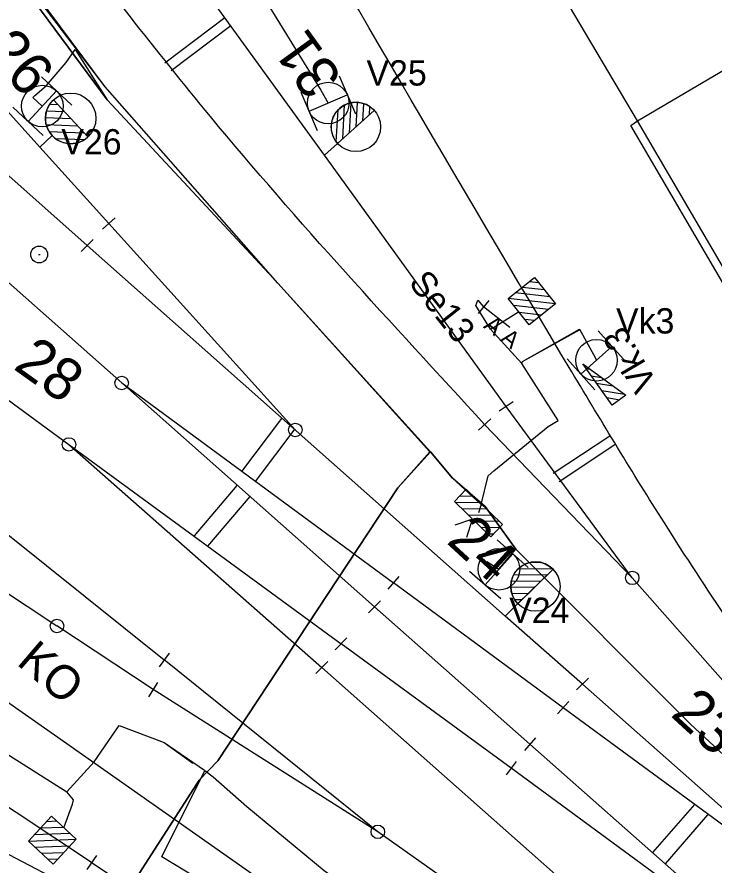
# Model space of a CAD drawing. Extents: x -496570 to -495506, y -1089156 to -1088046.
# Drawn here: x -496040.3 to -495999, y -1088592.2 to -1088542 of the extents above; entities that cross this region are included whole.
import ezdxf

# ---------------------------------------------------------------- set-up
doc = ezdxf.new("R2010")
doc.units = 0
for name, color, linetype in [('11', 7, 'Continuous'), ('14', 7, 'Continuous'), ('15', 7, 'Continuous'), ('20', 7, 'Continuous'), ('27', 7, 'Continuous'), ('39', 7, 'Continuous'), ('54', 7, 'Continuous'), ('PŮVODNÍ_NÁVRH', 7, 'Continuous'), ('SEE', 7, 'Continuous')]:
    doc.layers.add(name, color=color, linetype=linetype)

msp = doc.modelspace()

# ---------------------------------------------------------------- linework, layer by layer
at = {"layer": '11'}
for p, q in [((-496031.528, -1088544.679), (-496027.962, -1088541.996)), ((-496031.147, -1088545.144), (-496027.61, -1088542.482)), ((-496039.013, -1088556.033), (-496038.913, -1088556.033)), ((-496008.511, -1088568.976), (-496005.162, -1088566.778)), ((-496008.167, -1088569.467), (-496004.852, -1088567.292))]:
    msp.add_line(p, q, dxfattribs=at)
for points in [[(-496026.95, -1088568.883), (-496024.582, -1088565.738)], [(-496026.143, -1088569.473), (-496023.8, -1088566.361)], [(-496029.754, -1088572.697), (-496027.23, -1088569.715)], [(-496028.965, -1088573.313), (-496026.466, -1088570.361)], [(-496002.617, -1088591.447), (-496000.13, -1088588.596)], [(-496001.863, -1088592.105), (-495999.348, -1088589.222)]]:
    msp.add_lwpolyline(points, dxfattribs=at)
msp.add_circle((-496038.963, -1088556.033), 0.5, dxfattribs=at)
at = {"layer": '14'}
for p, q in [((-496034.834, -1088554.201), (-496038.935, -1088549.668)), ((-496055.342, -1088566.508), (-496037.913, -1088578.03)), ((-496007.924, -1088582.875), (-496017.979, -1088575.474)), ((-496019.1, -1088576.895), (-496009.888, -1088585.031)), ((-496006.781, -1088581.466), (-496011.354, -1088577.439)), ((-496032.216, -1088581.796), (-496037.913, -1088578.03)), ((-496011.01, -1088586.449), (-496021.082, -1088579.088)), ((-495993.785, -1088605.649), (-496022.225, -1088580.492))]:
    msp.add_line(p, q, dxfattribs=at)
for points in [[(-496036.118, -1088555.5), (-496048.975, -1088544.1), (-496066.196, -1088528.906), (-496086.152, -1088511.349), (-496104.929, -1088494.746), (-496123.588, -1088478.229), (-496142.293, -1088461.701), (-496160.965, -1088445.175), (-496179.891, -1088428.396), (-496198.214, -1088412.189), (-496217.292, -1088395.311), (-496245.811, -1088370.064), (-496264.918, -1088353.145), (-496281.988, -1088338.018), (-496302.247, -1088320.079), (-496322.57, -1088302.076), (-496341.966, -1088284.907), (-496360.552, -1088268.447), (-496378.713, -1088252.378), (-496398.4, -1088234.928), (-496416.447, -1088218.945), (-496437.668, -1088200.162), (-496456.103, -1088183.845), (-496474.042, -1088168.071)], [(-496011.29, -1088565.037), (-496022.068, -1088550.141), (-496029.461, -1088539.924), (-496036.884, -1088529.665), (-496046.952, -1088515.759), (-496054.33, -1088505.532), (-496061.713, -1088495.299), (-496072.458, -1088480.37)], [(-496075.31, -1088545), (-496052.489, -1088563.281), (-496031.561, -1088580.038)], [(-496035.857, -1088592.043), (-496044.874, -1088586.073), (-496053.125, -1088580.797), (-496061.169, -1088575.721), (-496076.529, -1088566.028)], [(-496063.029, -1088566.985), (-496037.138, -1088585.134), (-496023.296, -1088594.829), (-496003.341, -1088609.037)], [(-496037.513, -1088593.285), (-496040.369, -1088591.776), (-496048.068, -1088587.699), (-496063.641, -1088579.453)]]:
    msp.add_lwpolyline(points, dxfattribs=at)
msp.add_circle((-496037.913, -1088578.03), 0.4, dxfattribs=at)
for points in [[(-496012.573, -1088566.09), (-496028.822, -1088547.857), (-496038.151, -1088535.934), (-496051.597, -1088517.251)], [(-495994.179, -1088583.585), (-496001.925, -1088571.928), (-496007.411, -1088562.975), (-496027.558, -1088528.593)], [(-496009.526, -1088642.986), (-496015.368, -1088636.526), (-496021.579, -1088629.917), (-496040.398, -1088611.545), (-496052.231, -1088600.497), (-496064.07, -1088590.377), (-496077.737, -1088579.829), (-496084.463, -1088574.911)]]:
    msp.add_spline(points, degree=3, dxfattribs=at)
at = {"layer": '15'}
for p, q in [((-496021.201, -1088545.449), (-496020.226, -1088547.712)), ((-496038.836, -1088545.509), (-496037.039, -1088547.194)), ((-496039.623, -1088548.149), (-496037.937, -1088546.351)), ((-496023.464, -1088546.424), (-496022.489, -1088548.687)), ((-496022.977, -1088547.555), (-496020.713, -1088546.581)), ((-496040.521, -1088547.306), (-496038.724, -1088548.991)), ((-496009.03, -1088558.131), (-496010.349, -1088557.977)), ((-496009.359, -1088557.715), (-496009.933, -1088557.648)), ((-496008.7, -1088558.547), (-496010.765, -1088558.307)), ((-496008.371, -1088558.962), (-496011.181, -1088558.636)), ((-496008.787, -1088559.291), (-496010.852, -1088559.052)), ((-496009.203, -1088559.621), (-496010.522, -1088559.468)), ((-496009.619, -1088559.95), (-496010.193, -1088559.883)), ((-496005.854, -1088560.56), (-496004.21, -1088562.396)), ((-496006.868, -1088563.122), (-496005.032, -1088561.478)), ((-496007.69, -1088562.204), (-496006.046, -1088564.04)), ((-496006.564, -1088562.783), (-496006.328, -1088562.822)), ((-496006.255, -1088563.214), (-496005.649, -1088563.314)), ((-496005.946, -1088563.645), (-496004.97, -1088563.806)), ((-496005.636, -1088564.077), (-496004.291, -1088564.298)), ((-496005.328, -1088564.507), (-496004.573, -1088564.632)), ((-496005.019, -1088564.938), (-496005.003, -1088564.94)), ((-496011.834, -1088572.933), (-496009.99, -1088574.567)), ((-496012.546, -1088575.594), (-496010.912, -1088573.75)), ((-496013.468, -1088574.777), (-496011.624, -1088576.411)), ((-496038.521, -1088589.598), (-496037.943, -1088589.577)), ((-496038.882, -1088589.986), (-496037.555, -1088589.938)), ((-496039.244, -1088590.375), (-496037.166, -1088590.3)), ((-496039.605, -1088590.763), (-496036.778, -1088590.661)), ((-496039.217, -1088591.124), (-496037.139, -1088591.049)), ((-496038.828, -1088591.486), (-496037.501, -1088591.438)), ((-496038.44, -1088591.847), (-496037.862, -1088591.826))]:
    msp.add_line(p, q, dxfattribs=at)
for points in [[(-496009.939, -1088560.204), (-496011.181, -1088558.636), (-496009.613, -1088557.394), (-496008.371, -1088558.962)], [(-496009.939, -1088560.204), (-496011.181, -1088558.636), (-496009.613, -1088557.394), (-496008.371, -1088558.962)], [(-496038.242, -1088589.299), (-496036.778, -1088590.661), (-496038.141, -1088592.125), (-496039.605, -1088590.763)], [(-496038.242, -1088589.299), (-496036.778, -1088590.661), (-496038.141, -1088592.125), (-496039.605, -1088590.763)]]:
    msp.add_lwpolyline(points, close=True, dxfattribs=at)
for points in [[(-496009.939, -1088560.204), (-496011.181, -1088558.636), (-496009.613, -1088557.394), (-496008.371, -1088558.962), (-496009.939, -1088560.204)], [(-496009.939, -1088560.204), (-496011.181, -1088558.636), (-496009.613, -1088557.394), (-496008.371, -1088558.962), (-496009.939, -1088560.204)], [(-496006.761, -1088562.508), (-496004.2, -1088564.364), (-496005.013, -1088564.947), (-496006.761, -1088562.508)], [(-496006.761, -1088562.508), (-496004.2, -1088564.364), (-496005.013, -1088564.947), (-496006.761, -1088562.508)], [(-496038.242, -1088589.299), (-496036.778, -1088590.661), (-496038.141, -1088592.125), (-496039.605, -1088590.763), (-496038.242, -1088589.299)], [(-496038.242, -1088589.299), (-496036.778, -1088590.661), (-496038.141, -1088592.125), (-496039.605, -1088590.763), (-496038.242, -1088589.299)]]:
    msp.add_lwpolyline(points, dxfattribs=at)
for centre in [(-496021.841, -1088547.065), (-496038.778, -1088547.246), (-496005.947, -1088562.296), (-496011.727, -1088574.667)]:
    msp.add_circle(centre, 1.232, dxfattribs=at)
at = {"layer": '20'}
for p, q in [((-496012.331, -1088558.747), (-496012.949, -1088559.533)), ((-496011.082, -1088560.362), (-496012.64, -1088559.14))]:
    msp.add_line(p, q, dxfattribs=at)
at = {"layer": '27'}
for p, q in [((-496036.081, -1088549.071), (-496038.119, -1088546.869)), ((-496038.119, -1088546.869), (-496036.081, -1088549.071)), ((-496038.345, -1088547.139), (-496037.851, -1088547.159)), ((-496020.981, -1088549.175), (-496020.868, -1088547.18)), ((-496020.586, -1088548.822), (-496020.485, -1088547.049)), ((-496020.19, -1088548.468), (-496020.108, -1088547.027)), ((-496019.794, -1088548.115), (-496019.737, -1088547.102)), ((-496019.398, -1088547.762), (-496019.372, -1088547.285)), ((-496038.596, -1088547.93), (-496037.083, -1088547.989)), ((-496038.531, -1088547.532), (-496037.467, -1088547.574)), ((-496021.367, -1088549.368), (-496021.261, -1088547.473)), ((-496019.114, -1088547.509), (-496021.299, -1088549.458)), ((-496021.298, -1088549.458), (-496019.114, -1088547.509)), ((-496038.552, -1088548.333), (-496036.698, -1088548.404)), ((-496038.384, -1088548.74), (-496036.314, -1088548.819)), ((-496038.201, -1088548.989), (-496038.935, -1088549.668)), ((-496038.019, -1088549.154), (-496036.279, -1088549.221)), ((-496021.299, -1088549.459), (-496022.068, -1088550.141)), ((-496021.299, -1088549.458), (-496021.298, -1088549.458)), ((-496034.458, -1088553.871), (-496035.21, -1088554.531)), ((-496023.791, -1088566.421), (-496034.834, -1088554.201)), ((-496035.76, -1088555.151), (-496036.476, -1088555.849)), ((-496010.876, -1088564.756), (-496011.704, -1088565.318)), ((-496012.203, -1088565.754), (-496012.943, -1088566.426)), ((-496003.83, -1088575.183), (-496012.573, -1088566.09)), ((-496009.838, -1088574.256), (-496009.247, -1088574.263)), ((-496010.845, -1088574.984), (-496008.863, -1088575.008)), ((-496008.524, -1088574.675), (-496010.619, -1088576.719)), ((-496008.516, -1088574.67), (-496010.612, -1088576.713)), ((-496010.554, -1088574.617), (-496008.546, -1088574.642)), ((-496008.517, -1088574.669), (-496008.516, -1088574.67)), ((-496017.656, -1088575.092), (-496018.302, -1088575.856)), ((-496010.986, -1088575.352), (-496009.238, -1088575.374)), ((-496011.024, -1088575.721), (-496009.613, -1088575.738)), ((-496018.752, -1088576.536), (-496019.448, -1088577.254)), ((-496010.968, -1088576.092), (-496009.987, -1088576.104)), ((-496010.803, -1088576.464), (-496010.362, -1088576.47)), ((-496010.62, -1088576.719), (-496011.354, -1088577.439)), ((-496020.735, -1088578.728), (-496021.429, -1088579.448)), ((-496031.268, -1088579.633), (-496031.854, -1088580.443)), ((-496021.873, -1088580.137), (-496022.577, -1088580.847)), ((-496031.953, -1088581.371), (-496032.479, -1088582.221)), ((-496006.428, -1088581.112), (-496007.134, -1088581.82)), ((-496007.584, -1088582.509), (-496008.264, -1088583.241)), ((-496009.563, -1088584.651), (-496010.213, -1088585.411)), ((-496010.716, -1088586.045), (-496011.304, -1088586.853)), ((-496035.576, -1088591.63), (-496036.138, -1088592.456))]:
    msp.add_line(p, q, dxfattribs=at)
for points in [[(-496022.068, -1088550.141), (-496029.461, -1088539.924), (-496036.884, -1088529.665)], [(-496038.935, -1088549.668), (-496047.32, -1088540.34), (-496055.467, -1088530.486)], [(-496019.1, -1088576.895), (-496034.077, -1088563.64), (-496044.26, -1088554.627)], [(-496011.354, -1088577.439), (-496036.118, -1088555.5)], [(-496048.18, -1088559.237), (-496037.202, -1088567.279), (-496021.082, -1088579.088)], [(-496034.077, -1088563.64), (-496017.979, -1088575.474)], [(-495995.487, -1088584.64), (-496003.83, -1088575.183), (-496011.29, -1088565.037)], [(-496037.202, -1088567.279), (-496022.225, -1088580.492)], [(-496005.328, -1088599.803), (-496018.9, -1088590.217), (-496031.561, -1088580.038)], [(-495981.593, -1088603.731), (-495991.789, -1088594.718), (-496006.781, -1088581.466)], [(-496018.9, -1088590.217), (-496032.216, -1088581.796)], [(-495991.789, -1088594.718), (-496007.924, -1088582.875)], [(-495984.692, -1088607.313), (-495994.886, -1088598.298), (-496009.888, -1088585.031)], [(-495994.886, -1088598.298), (-496011.01, -1088586.449)], [(-496035.857, -1088592.043), (-496006.149, -1088611.82)]]:
    msp.add_lwpolyline(points, dxfattribs=at)
for centre, radius in [((-496037.1, -1088547.97), 1.5), ((-496020.202, -1088548.477), 1.462), ((-496034.077, -1088563.64), 0.4), ((-496023.791, -1088566.421), 0.4), ((-496037.202, -1088567.279), 0.4), ((-496009.565, -1088575.692), 1.462), ((-496003.83, -1088575.183), 0.4), ((-496018.9, -1088590.217), 0.4)]:
    msp.add_circle(centre, radius, dxfattribs=at)
for centre, radius, start, end in [((-496037.1, -1088547.97), 1.5, 132.7844, 312.7844), ((-496020.207, -1088548.483), 1.464, 41.7598, 221.7206), ((-496009.564, -1088575.691), 1.464, 44.3218, 224.2827)]:
    msp.add_arc(centre, radius, start, end, dxfattribs=at)
at = {"layer": '39'}
for points in [[(-495974.045, -1088579.399), (-495982.418, -1088584.284), (-495997.256, -1088558.819), (-496003.517, -1088548.12), (-496034.293, -1088496.252), (-496025.968, -1088491.27), (-495995.168, -1088543.196), (-495974.045, -1088579.399)], [(-496003.517, -1088548.12), (-495995.168, -1088543.196)], [(-495997.256, -1088558.819), (-495997.66, -1088559.09), (-496003.906, -1088548.391), (-496003.517, -1088548.12)]]:
    msp.add_lwpolyline(points, dxfattribs=at)
at = {"layer": '54'}
for p, q in [((-496013.614, -1088569.982), (-496013.713, -1088569.983)), ((-496013.234, -1088570.351), (-496014.083, -1088570.363)), ((-496012.854, -1088570.721), (-496014.268, -1088570.741)), ((-496012.78, -1088570.83), (-496012.937, -1088571.337)), ((-496012.473, -1088571.091), (-496013.887, -1088571.111)), ((-496012.093, -1088571.46), (-496013.507, -1088571.48)), ((-496011.713, -1088571.829), (-496013.127, -1088571.85)), ((-496011.688, -1088572.204), (-496012.746, -1088572.22)), ((-496012.058, -1088572.584), (-496012.366, -1088572.589))]:
    msp.add_line(p, q, dxfattribs=at)
for points in [[(-496165.07, -1088482.9), (-496156.87, -1088489.91), (-496145.17, -1088500.37), (-496132.17, -1088511.64), (-496132.14, -1088511.95), (-496109.93, -1088531.36), (-496085.16, -1088553.21), (-496080.73, -1088556.99), (-496073.59, -1088563.01), (-496067.7, -1088567.42), (-496060.271, -1088572.567), (-496056.99, -1088574.85), (-496054.978, -1088576.218), (-496044.9, -1088583.07), (-496037.32, -1088587.86), (-496035.7, -1088586.08), (-496034.22, -1088583.93), (-496031.57, -1088584.92), (-496029.17, -1088586.56)], [(-496037.63, -1088519.866), (-496029.46, -1088534.646), (-496022.279, -1088546.306), (-496021.845, -1088547.068)], [(-495936.743, -1088670.436), (-495952.112, -1088656.757), (-495966.13, -1088641.736), (-495969.086, -1088638.597), (-495972.985, -1088642.454), (-495974.115, -1088643.402), (-495977.11, -1088640.04), (-495990.27, -1088628.8), (-496002.7, -1088620.53), (-496005.33, -1088618.88), (-496012.58, -1088612.9), (-496012.99, -1088612.61), (-496013.61, -1088612.22), (-496021.18, -1088608.07), (-496022.438, -1088607.407), (-496036.409, -1088599.224), (-496036.551, -1088598.154), (-496029.489, -1088587.165), (-496028.39, -1088586.02), (-496017.71, -1088569.84), (-496015.829, -1088567.72), (-496024.83, -1088557.73), (-496035.05, -1088546.1), (-496051.31, -1088524.79)], [(-496051.31, -1088524.79), (-496034.93, -1088546.87), (-496024.83, -1088557.73), (-496015.783, -1088567.718), (-496017.71, -1088569.84), (-496028.39, -1088586.02), (-496029.489, -1088587.165), (-496036.551, -1088598.154), (-496036.409, -1088599.224), (-496022.438, -1088607.407), (-496021.18, -1088608.07), (-496013.61, -1088612.22), (-496012.58, -1088612.9), (-496008.281, -1088616.445), (-496005.33, -1088618.88), (-496003.57, -1088619.88), (-496002.7, -1088620.53), (-495990.27, -1088628.8), (-495988.28, -1088630.5), (-495980.92, -1088636.9), (-495977.11, -1088640.04), (-495974.115, -1088643.402)], [(-496017.181, -1088617.602), (-496012.99, -1088612.61), (-496021.18, -1088608.07), (-496022.438, -1088607.407), (-496036.409, -1088599.224), (-496036.551, -1088598.154), (-496029.489, -1088587.165), (-496028.39, -1088586.02), (-496017.71, -1088569.84), (-496015.829, -1088567.72), (-496024.83, -1088557.73), (-496035.05, -1088546.1), (-496051.01, -1088524.68)], [(-496038.78, -1088547.25), (-496039.34, -1088546.74), (-496039.23, -1088546.62), (-496038.55, -1088546.04), (-496037.37, -1088544.67), (-496036.84, -1088543.89), (-496034.93, -1088546.87)], [(-496010.37, -1088562.48), (-496012.22, -1088560.45), (-496013.1, -1088559.06), (-496012.97, -1088558.73), (-496012.64, -1088559.14)], [(-496012.22, -1088560.45), (-496012.04, -1088560.35), (-496010.56, -1088559.42)], [(-496015.783, -1088567.718), (-496014.475, -1088569.283), (-496012.78, -1088570.83), (-496012.36, -1088569.13), (-496012.03, -1088568.84), (-496008.81, -1088566.22), (-496008.21, -1088565.86), (-496010.37, -1088562.48), (-496010.33, -1088562.36), (-496006.96, -1088560.49), (-496006.95, -1088560.45), (-496006.02, -1088562.13), (-496005.95, -1088562.3)], [(-496012.21, -1088572.741), (-496014.361, -1088570.65), (-496013.664, -1088569.933), (-496011.513, -1088572.024), (-496012.21, -1088572.741)], [(-496012.78, -1088570.83), (-496012.549, -1088570.954), (-496010.733, -1088573.476), (-496000.372, -1088583.843), (-495993.339, -1088590.372), (-495988.204, -1088586.901), (-495977.95, -1088599.48), (-495977.304, -1088600.272), (-495972.198, -1088606.466), (-495968.157, -1088609.856), (-495963.452, -1088613.618), (-495960.741, -1088615.623), (-495955.49, -1088620.73), (-495954.76, -1088621.51), (-495953.449, -1088622.609), (-495941.984, -1088632.338)], [(-496013.624, -1088572.761), (-496013.285, -1088571.696), (-496014.341, -1088572.064)], [(-496012.45, -1088574.22), (-496011.729, -1088574.672), (-496010.733, -1088573.476)], [(-496027.54, -1088595.45), (-496027.07, -1088595.95), (-496026.97, -1088595.75), (-496026.49, -1088594.86), (-496031.7, -1088591.7), (-496029.151, -1088586.587)], [(-496029.151, -1088586.587), (-496028.657, -1088586.958), (-496026.671, -1088588.724), (-496022.09, -1088592.506), (-496010.962, -1088600.371), (-496008.713, -1088601.961), (-496007.3, -1088600.45), (-496007.889, -1088600.131)], [(-496037.51, -1088589.98), (-496036.99, -1088588.58), (-496036.94, -1088588.33), (-496037.32, -1088587.86)]]:
    msp.add_lwpolyline(points, dxfattribs=at)
msp.add_lwpolyline([(-496012.21, -1088572.741), (-496014.361, -1088570.65), (-496013.664, -1088569.933), (-496011.513, -1088572.024)], close=True, dxfattribs=at)
at = {"layer": 'PŮVODNÍ_NÁVRH'}
for p, q in [((-496010.33, -1088562.36), (-496006.95, -1088560.45)), ((-496012.03, -1088568.84), (-496008.81, -1088566.22)), ((-496028.657, -1088586.958), (-496026.671, -1088588.724))]:
    msp.add_line(p, q, dxfattribs=at)
for points in [[(-496015.829, -1088567.72), (-496024.83, -1088557.73), (-496034.93, -1088546.87), (-496051.31, -1088524.79), (-496051.95, -1088524), (-496075.35, -1088495.41), (-496082.21, -1088487.56), (-496083.78, -1088486.19), (-496093.74, -1088475.27), (-496115.78, -1088449.34)], [(-495974.115, -1088643.402), (-495977.11, -1088640.04), (-495980.92, -1088636.9), (-495990.27, -1088628.8), (-496002.7, -1088620.53), (-496005.33, -1088618.88), (-496012.58, -1088612.9), (-496013.61, -1088612.22), (-496021.18, -1088608.07), (-496022.438, -1088607.407), (-496036.409, -1088599.224), (-496036.952, -1088598.948), (-496036.551, -1088598.154), (-496029.489, -1088587.165), (-496028.39, -1088586.02), (-496017.71, -1088569.84), (-496015.829, -1088567.72)], [(-496037.32, -1088587.86), (-496035.7, -1088586.08), (-496034.22, -1088583.93), (-496031.57, -1088584.92), (-496029.86, -1088586.15)]]:
    msp.add_lwpolyline(points, dxfattribs=at)
at = {"layer": 'SEE'}
for points in [[(-496051.31, -1088524.79), (-496034.93, -1088546.87), (-496024.83, -1088557.73), (-496015.829, -1088567.72), (-496017.71, -1088569.84), (-496028.39, -1088586.02), (-496029.489, -1088587.165), (-496036.551, -1088598.154), (-496036.952, -1088598.948), (-496036.409, -1088599.224), (-496022.438, -1088607.407), (-496021.18, -1088608.07), (-496013.61, -1088612.22), (-496012.58, -1088612.9), (-496005.33, -1088618.88), (-496002.7, -1088620.53), (-495990.27, -1088628.8), (-495980.92, -1088636.9), (-495977.11, -1088640.04), (-495975.448, -1088642.109)], [(-496051.31, -1088524.79), (-496034.93, -1088546.87), (-496024.83, -1088557.73), (-496015.829, -1088567.72), (-496017.71, -1088569.84), (-496028.39, -1088586.02), (-496029.489, -1088587.165), (-496036.551, -1088598.154), (-496036.952, -1088598.948), (-496036.409, -1088599.224), (-496022.438, -1088607.407), (-496021.18, -1088608.07), (-496013.61, -1088612.22), (-496012.58, -1088612.9), (-496005.33, -1088618.88), (-496002.7, -1088620.53), (-495990.27, -1088628.8), (-495980.92, -1088636.9), (-495977.11, -1088640.04), (-495974.115, -1088643.402)], [(-495955.217, -1088615.433), (-495959.856, -1088615.966), (-495960.741, -1088615.623), (-495963.452, -1088613.618), (-495968.157, -1088609.856), (-495972.198, -1088606.466), (-495975.687, -1088602.234), (-495977.304, -1088600.272), (-495988.204, -1088586.901), (-495993.339, -1088590.372), (-496000.372, -1088583.843), (-496010.733, -1088573.476), (-496012.549, -1088570.954), (-496014.475, -1088569.283), (-496015.783, -1088567.718)]]:
    msp.add_lwpolyline(points, dxfattribs=at)

# ---------------------------------------------------------------- texts
at = {"layer": '14'}
msp.add_text('KO', height=2, rotation=319.4182, dxfattribs=at).set_placement((-496040.362, -1088580.266))
at = {"layer": '15'}
for s, p in [('V25', (-496019.574, -1088546.029)), ('V26', (-496037.652, -1088550.109)), ('Vk3', (-496004.79, -1088560.712)), ('V24', (-496011.12, -1088577.851))]:
    msp.add_text(s, height=1.5, dxfattribs=at).set_placement(p)
msp.add_text('Vk.3', height=1.5, rotation=120.3766, dxfattribs=at).set_placement((-496002.32, -1088563.64))
at = {"layer": '20'}
for s, height, rotation, p in [('Se13', 1.5, 308.4138, (-496017.122, -1088557.73)), ('  A A', 1, 321.8897, (-496013.275, -1088559.88))]:
    msp.add_text(s, height=height, rotation=rotation, dxfattribs=at).set_placement(p)
at = {"layer": '27'}
for s, rotation, p in [('26', 312.6217, (-496042.265, -1088544.097)), ('31', 125.888, (-496020.953, -1088545.56)), ('28', 324.4824, (-496040.562, -1088562.767)), ('24', 317.4452, (-496014.895, -1088573.078)), ('23', 317.4452, (-496001.619, -1088583.324))]:
    msp.add_text(s, height=2.5, rotation=rotation, dxfattribs=at).set_placement(p)

doc.saveas('drawing.dxf')
